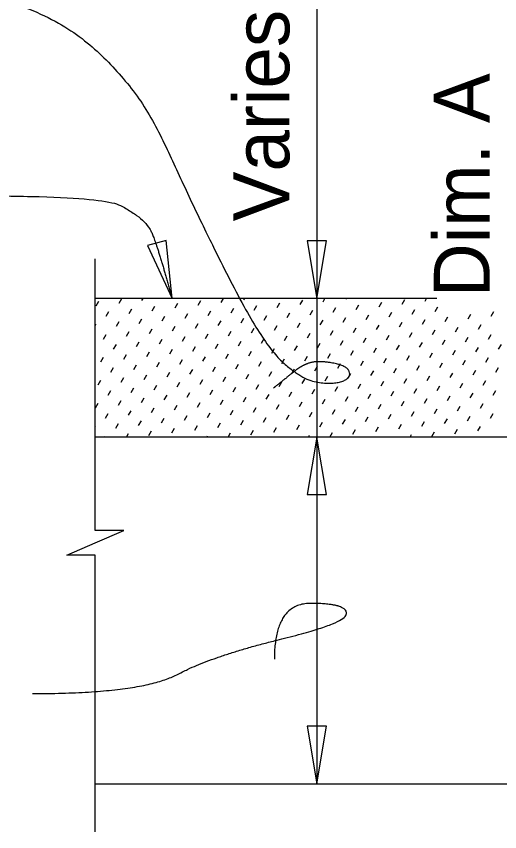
# Model space of a CAD drawing. Extents: x 21516.9 to 21589, y 56156.6 to 56194.3.
# Drawn here: x 21541.577 to 21543.323, y 56181.286 to 56184.232 of the extents above; entities that cross this region are included whole.
import ezdxf

# ---------------------------------------------------------------- set-up
doc = ezdxf.new("R2010")
doc.units = 0
for name, color, linetype in [('AdhocPoint_dp', 7, 'Continuous'), ('Patterning', 7, 'Continuous'), ('PlotBorder_dp', 7, 'Continuous'), ('SheetBorder_dp', 7, 'Continuous')]:
    doc.layers.add(name, color=color, linetype=linetype)

msp = doc.modelspace()

# ---------------------------------------------------------------- linework, layer by layer
at = {"layer": 'AdhocPoint_dp'}
for p, q in [((21545.7957, 56182.7117), (21541.8624, 56182.7117)), ((21541.8624, 56181.4587), (21548.1773, 56181.4587))]:
    msp.add_line(p, q, dxfattribs=at)
at = {"layer": 'Patterning'}
for p, q in [((21543.0953, 56183.2117), (21541.8624, 56183.2117)), ((21541.9481, 56183.195), (21541.9578, 56183.2117)), ((21542.031, 56183.2047), (21542.0351, 56183.2117)), ((21542.2335, 56183.1876), (21542.2432, 56183.2044)), ((21542.3165, 56183.1973), (21542.3248, 56183.2117)), ((21542.3994, 56183.207), (21542.4021, 56183.2117)), ((21542.6019, 56183.1898), (21542.6116, 56183.2066)), ((21542.6848, 56183.1996), (21542.6919, 56183.2117)), ((21542.7678, 56183.2093), (21542.7692, 56183.2117)), ((21542.9702, 56183.1921), (21542.98, 56183.2089)), ((21543.0532, 56183.2019), (21543.0589, 56183.2117)), ((21541.8652, 56183.1853), (21541.8749, 56183.2021)), ((21541.9847, 56183.1584), (21541.9944, 56183.1752)), ((21542.0676, 56183.1681), (21542.0774, 56183.1849)), ((21542.1506, 56183.1778), (21542.1603, 56183.1946)), ((21542.3531, 56183.1607), (21542.3628, 56183.1775)), ((21542.436, 56183.1704), (21542.4457, 56183.1872)), ((21542.5189, 56183.1801), (21542.5287, 56183.1969)), ((21542.7214, 56183.163), (21542.7311, 56183.1798)), ((21542.8044, 56183.1727), (21542.8141, 56183.1895)), ((21542.8873, 56183.1824), (21542.897, 56183.1992)), ((21543.0898, 56183.1652), (21543.0995, 56183.182)), ((21541.9018, 56183.1487), (21541.9115, 56183.1655)), ((21542.1043, 56183.1315), (21542.114, 56183.1483)), ((21542.1872, 56183.1412), (21542.1969, 56183.158)), ((21542.2701, 56183.151), (21542.2799, 56183.1677)), ((21542.4726, 56183.1338), (21542.4823, 56183.1506)), ((21542.5555, 56183.1435), (21542.5653, 56183.1603)), ((21542.6385, 56183.1532), (21542.6482, 56183.17)), ((21542.841, 56183.1361), (21542.8507, 56183.1529)), ((21542.9239, 56183.1458), (21542.9336, 56183.1626)), ((21543.0068, 56183.1555), (21543.0166, 56183.1723)), ((21543.1264, 56183.1286), (21543.1361, 56183.1454)), ((21543.2093, 56183.1384), (21543.219, 56183.1552)), ((21543.2923, 56183.1481), (21543.302, 56183.1649)), ((21541.8624, 56183.1143), (21541.8652, 56183.1191)), ((21541.9384, 56183.1121), (21541.9481, 56183.1289)), ((21542.0213, 56183.1218), (21542.031, 56183.1386)), ((21542.2238, 56183.1046), (21542.2335, 56183.1214)), ((21542.3067, 56183.1143), (21542.3165, 56183.1311)), ((21542.3897, 56183.1241), (21542.3994, 56183.1409)), ((21542.5922, 56183.1069), (21542.6019, 56183.1237)), ((21542.6751, 56183.1166), (21542.6848, 56183.1334)), ((21542.758, 56183.1264), (21542.7678, 56183.1431)), ((21542.8776, 56183.0995), (21542.8873, 56183.1163)), ((21542.9605, 56183.1092), (21542.9702, 56183.126)), ((21543.0435, 56183.1189), (21543.0532, 56183.1357)), ((21543.2459, 56183.1018), (21543.2557, 56183.1185)), ((21541.975, 56183.0755), (21541.9847, 56183.0923)), ((21542.0579, 56183.0852), (21542.0676, 56183.102)), ((21542.1409, 56183.0949), (21542.1506, 56183.1117)), ((21542.3433, 56183.0777), (21542.3531, 56183.0945)), ((21542.4263, 56183.0875), (21542.436, 56183.1043)), ((21542.5092, 56183.0972), (21542.5189, 56183.114)), ((21542.6288, 56183.0703), (21542.6385, 56183.0871)), ((21542.7117, 56183.08), (21542.7214, 56183.0968)), ((21542.7946, 56183.0897), (21542.8044, 56183.1065)), ((21542.9971, 56183.0726), (21543.0068, 56183.0894)), ((21543.0801, 56183.0823), (21543.0898, 56183.0991)), ((21543.163, 56183.092), (21543.1727, 56183.1088)), ((21541.892, 56183.0657), (21541.9018, 56183.0825)), ((21542.0945, 56183.0486), (21542.1043, 56183.0654)), ((21542.1775, 56183.0583), (21542.1872, 56183.0751)), ((21542.2604, 56183.068), (21542.2701, 56183.0848)), ((21542.3799, 56183.0411), (21542.3897, 56183.0579)), ((21542.4629, 56183.0509), (21542.4726, 56183.0676)), ((21542.5458, 56183.0606), (21542.5555, 56183.0774)), ((21542.7483, 56183.0434), (21542.758, 56183.0602)), ((21542.8312, 56183.0531), (21542.841, 56183.0699)), ((21542.9142, 56183.0629), (21542.9239, 56183.0797)), ((21543.1167, 56183.0457), (21543.1264, 56183.0625)), ((21543.1996, 56183.0554), (21543.2093, 56183.0722)), ((21543.2825, 56183.0651), (21543.2923, 56183.0819)), ((21541.9287, 56183.0291), (21541.9384, 56183.0459)), ((21542.0116, 56183.0388), (21542.0213, 56183.0556)), ((21542.1311, 56183.012), (21542.1409, 56183.0288)), ((21542.2141, 56183.0217), (21542.2238, 56183.0385)), ((21542.297, 56183.0314), (21542.3067, 56183.0482)), ((21542.4995, 56183.0142), (21542.5092, 56183.031)), ((21542.5824, 56183.024), (21542.5922, 56183.0408)), ((21542.6654, 56183.0337), (21542.6751, 56183.0505)), ((21542.8679, 56183.0165), (21542.8776, 56183.0333)), ((21542.9508, 56183.0263), (21542.9605, 56183.043)), ((21543.0337, 56183.036), (21543.0435, 56183.0528)), ((21543.2362, 56183.0188), (21543.2459, 56183.0356)), ((21543.3191, 56183.0285), (21543.3289, 56183.0453)), ((21541.8823, 56182.9828), (21541.892, 56182.9996)), ((21541.9653, 56182.9925), (21541.975, 56183.0093)), ((21542.0482, 56183.0022), (21542.0579, 56183.019)), ((21542.2507, 56182.9851), (21542.2604, 56183.0019)), ((21542.3336, 56182.9948), (21542.3433, 56183.0116)), ((21542.4166, 56183.0045), (21542.4263, 56183.0213)), ((21542.619, 56182.9874), (21542.6288, 56183.0042)), ((21542.702, 56182.9971), (21542.7117, 56183.0139)), ((21542.7849, 56183.0068), (21542.7946, 56183.0236)), ((21542.9874, 56182.9896), (21542.9971, 56183.0064)), ((21543.0703, 56182.9994), (21543.0801, 56183.0162)), ((21543.1533, 56183.0091), (21543.163, 56183.0259)), ((21543.2728, 56182.9822), (21543.2825, 56182.999)), ((21542.0019, 56182.9559), (21542.0116, 56182.9727)), ((21542.0848, 56182.9656), (21542.0945, 56182.9824)), ((21542.1677, 56182.9754), (21542.1775, 56182.9922)), ((21542.3702, 56182.9582), (21542.3799, 56182.975)), ((21542.4532, 56182.9679), (21542.4629, 56182.9847)), ((21542.5361, 56182.9776), (21542.5458, 56182.9944)), ((21542.7386, 56182.9605), (21542.7483, 56182.9773)), ((21542.8215, 56182.9702), (21542.8312, 56182.987)), ((21542.9045, 56182.9799), (21542.9142, 56182.9967)), ((21543.024, 56182.953), (21543.0337, 56182.9698)), ((21543.1069, 56182.9628), (21543.1167, 56182.9796)), ((21543.1899, 56182.9725), (21543.1996, 56182.9893)), ((21541.9189, 56182.9462), (21541.9287, 56182.963)), ((21542.1214, 56182.929), (21542.1311, 56182.9458)), ((21542.2044, 56182.9387), (21542.2141, 56182.9555)), ((21542.2873, 56182.9485), (21542.297, 56182.9653)), ((21542.4898, 56182.9313), (21542.4995, 56182.9481)), ((21542.5727, 56182.941), (21542.5824, 56182.9578)), ((21542.6556, 56182.9508), (21542.6654, 56182.9675)), ((21542.7752, 56182.9239), (21542.7849, 56182.9407)), ((21542.8581, 56182.9336), (21542.8679, 56182.9504)), ((21542.9411, 56182.9433), (21542.9508, 56182.9601)), ((21543.1436, 56182.9262), (21543.1533, 56182.9429)), ((21543.2265, 56182.9359), (21543.2362, 56182.9527)), ((21543.3094, 56182.9456), (21543.3191, 56182.9624)), ((21541.8726, 56182.8999), (21541.8823, 56182.9167)), ((21541.9555, 56182.9096), (21541.9653, 56182.9264)), ((21542.0385, 56182.9193), (21542.0482, 56182.9361)), ((21542.241, 56182.9021), (21542.2507, 56182.9189)), ((21542.3239, 56182.9119), (21542.3336, 56182.9287)), ((21542.4068, 56182.9216), (21542.4166, 56182.9384)), ((21542.5264, 56182.8947), (21542.5361, 56182.9115)), ((21542.6093, 56182.9044), (21542.619, 56182.9212)), ((21542.6923, 56182.9141), (21542.702, 56182.9309)), ((21542.8947, 56182.897), (21542.9045, 56182.9138)), ((21542.9777, 56182.9067), (21542.9874, 56182.9235)), ((21543.0606, 56182.9164), (21543.0703, 56182.9332)), ((21543.2631, 56182.8993), (21543.2728, 56182.9161)), ((21541.9921, 56182.873), (21542.0019, 56182.8898)), ((21542.0751, 56182.8827), (21542.0848, 56182.8995)), ((21542.158, 56182.8924), (21542.1677, 56182.9092)), ((21542.2776, 56182.8655), (21542.2873, 56182.8823)), ((21542.3605, 56182.8753), (21542.3702, 56182.8921)), ((21542.4434, 56182.885), (21542.4532, 56182.9018)), ((21542.6459, 56182.8678), (21542.6556, 56182.8846)), ((21542.7289, 56182.8775), (21542.7386, 56182.8943)), ((21542.8118, 56182.8873), (21542.8215, 56182.9041)), ((21543.0143, 56182.8701), (21543.024, 56182.8869)), ((21543.0972, 56182.8798), (21543.1069, 56182.8966)), ((21543.1802, 56182.8895), (21543.1899, 56182.9063)), ((21541.9092, 56182.8633), (21541.9189, 56182.88)), ((21542.0288, 56182.8364), (21542.0385, 56182.8532)), ((21542.1117, 56182.8461), (21542.1214, 56182.8629)), ((21542.1946, 56182.8558), (21542.2044, 56182.8726)), ((21542.3971, 56182.8387), (21542.4068, 56182.8554)), ((21542.48, 56182.8484), (21542.4898, 56182.8652)), ((21542.563, 56182.8581), (21542.5727, 56182.8749)), ((21542.7655, 56182.8409), (21542.7752, 56182.8577)), ((21542.8484, 56182.8507), (21542.8581, 56182.8674)), ((21542.9313, 56182.8604), (21542.9411, 56182.8772)), ((21543.1338, 56182.8432), (21543.1436, 56182.86)), ((21543.2168, 56182.8529), (21543.2265, 56182.8697)), ((21543.2997, 56182.8627), (21543.3094, 56182.8795)), ((21541.8629, 56182.8169), (21541.8726, 56182.8337)), ((21541.9458, 56182.8266), (21541.9555, 56182.8434)), ((21542.1483, 56182.8095), (21542.158, 56182.8263)), ((21542.2312, 56182.8192), (21542.241, 56182.836)), ((21542.3142, 56182.8289), (21542.3239, 56182.8457)), ((21542.5167, 56182.8118), (21542.5264, 56182.8286)), ((21542.5996, 56182.8215), (21542.6093, 56182.8383)), ((21542.6825, 56182.8312), (21542.6923, 56182.848)), ((21542.885, 56182.814), (21542.8947, 56182.8308)), ((21542.968, 56182.8238), (21542.9777, 56182.8406)), ((21543.0509, 56182.8335), (21543.0606, 56182.8503)), ((21543.1704, 56182.8066), (21543.1802, 56182.8234)), ((21543.2534, 56182.8163), (21543.2631, 56182.8331)), ((21541.8995, 56182.7803), (21541.9092, 56182.7971)), ((21541.9824, 56182.79), (21541.9921, 56182.8068)), ((21542.0654, 56182.7998), (21542.0751, 56182.8166)), ((21542.2678, 56182.7826), (21542.2776, 56182.7994)), ((21542.3508, 56182.7923), (21542.3605, 56182.8091)), ((21542.4337, 56182.802), (21542.4434, 56182.8188)), ((21542.5533, 56182.7752), (21542.563, 56182.792)), ((21542.6362, 56182.7849), (21542.6459, 56182.8017)), ((21542.7191, 56182.7946), (21542.7289, 56182.8114)), ((21542.8021, 56182.8043), (21542.8118, 56182.8211)), ((21542.9216, 56182.7774), (21542.9313, 56182.7942)), ((21543.0046, 56182.7872), (21543.0143, 56182.804)), ((21543.0875, 56182.7969), (21543.0972, 56182.8137)), ((21543.29, 56182.7797), (21543.2997, 56182.7965)), ((21542.019, 56182.7534), (21542.0288, 56182.7702)), ((21542.102, 56182.7632), (21542.1117, 56182.7799)), ((21542.1849, 56182.7729), (21542.1946, 56182.7897)), ((21542.3045, 56182.746), (21542.3142, 56182.7628)), ((21542.3874, 56182.7557), (21542.3971, 56182.7725)), ((21542.4703, 56182.7654), (21542.48, 56182.7822)), ((21542.6728, 56182.7483), (21542.6825, 56182.7651)), ((21542.7557, 56182.758), (21542.7655, 56182.7748)), ((21542.8387, 56182.7677), (21542.8484, 56182.7845)), ((21543.0412, 56182.7506), (21543.0509, 56182.7674)), ((21543.1241, 56182.7603), (21543.1338, 56182.7771)), ((21543.207, 56182.77), (21543.2168, 56182.7868)), ((21541.8624, 56182.7499), (21541.8629, 56182.7508)), ((21541.9361, 56182.7437), (21541.9458, 56182.7605)), ((21542.0556, 56182.7168), (21542.0654, 56182.7336)), ((21542.1386, 56182.7265), (21542.1483, 56182.7433)), ((21542.2215, 56182.7363), (21542.2312, 56182.7531)), ((21542.424, 56182.7191), (21542.4337, 56182.7359)), ((21542.5069, 56182.7288), (21542.5167, 56182.7456)), ((21542.5899, 56182.7386), (21542.5996, 56182.7553)), ((21542.7924, 56182.7214), (21542.8021, 56182.7382)), ((21542.8753, 56182.7311), (21542.885, 56182.7479)), ((21542.9582, 56182.7408), (21542.968, 56182.7576)), ((21543.1607, 56182.7237), (21543.1704, 56182.7405)), ((21543.2437, 56182.7334), (21543.2534, 56182.7502)), ((21541.8981, 56182.7117), (21541.8995, 56182.7142)), ((21541.9754, 56182.7117), (21541.9824, 56182.7239)), ((21542.2651, 56182.7117), (21542.2678, 56182.7165)), ((21542.3424, 56182.7117), (21542.3508, 56182.7262)), ((21542.6322, 56182.7117), (21542.6362, 56182.7187)), ((21542.7095, 56182.7117), (21542.7191, 56182.7285)), ((21542.9992, 56182.7117), (21543.0046, 56182.721)), ((21543.0778, 56182.7139), (21543.0875, 56182.7307)), ((21543.2889, 56182.7117), (21543.29, 56182.7136))]:
    msp.add_line(p, q, dxfattribs=at)
at = {"layer": 'PlotBorder_dp'}
msp.add_line((21542.6627, 56188.5451), (21542.6627, 56181.4587), dxfattribs=at)
for points in [[(21542.1401, 56183.2117), (21542.1188, 56183.4219), (21542.0508, 56183.4032)], [(21542.6626, 56183.2117), (21542.6979, 56183.42), (21542.6274, 56183.42)], [(21542.6626, 56182.7117), (21542.6274, 56182.5035), (21542.6979, 56182.5035)], [(21542.6626, 56181.4587), (21542.6979, 56181.6669), (21542.6274, 56181.6669)]]:
    msp.add_lwpolyline(points, close=True, dxfattribs=at)
msp.add_lwpolyline([(21541.8625, 56181.2858), (21541.8625, 56182.2845), (21541.7591, 56182.2845), (21541.8625, 56182.3295), (21541.9658, 56182.3745), (21541.8625, 56182.3745), (21541.8625, 56183.3551)], dxfattribs=at)
for points in [[(21540.7664, 56184.4386), (21541.5435, 56184.3438), (21542.0003, 56184.0192), (21542.2277, 56183.5171), (21542.4651, 56183.0503), (21542.6069, 56182.9198), (21542.7118, 56182.9014), (21542.7812, 56182.9199), (21542.7812, 56182.961), (21542.7104, 56182.9837), (21542.6239, 56182.9837), (21542.5332, 56182.9099), (21542.5063, 56182.8886)], [(21541.0103, 56183.5785), (21541.8538, 56183.5955), (21542.043, 56183.5039), (21542.089, 56183.397), (21542.1401, 56183.2117)], [(21541.6361, 56181.7848), (21542.027, 56181.7848), (21542.2876, 56181.9216), (21542.7697, 56182.0388), (21542.7697, 56182.1105), (21542.5091, 56182.1105), (21542.5091, 56181.9085)]]:
    msp.add_open_spline(points, degree=2, dxfattribs=at)

# ---------------------------------------------------------------- texts
at = {"layer": 'SheetBorder_dp'}
for s, p in [('Varies 1\'-9" to 2\'-0"', (21542.5631, 56183.4908)), ('Dim. A', (21543.2865, 56183.2169))]:
    msp.add_text(s, height=0.2016, rotation=90, dxfattribs=at).set_placement(p)

doc.saveas('drawing.dxf')
